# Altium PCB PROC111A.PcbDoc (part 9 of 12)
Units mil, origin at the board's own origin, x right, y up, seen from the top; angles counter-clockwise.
Board outline 7700 x 2300 mil, 6 copper layers (Top Layer, GND 1, SIG 1, SIG 2, GND 2, Bottom Layer), stack 61.062 mil thick; 841 components, 632 nets, 2914 pads, 1627 vias.
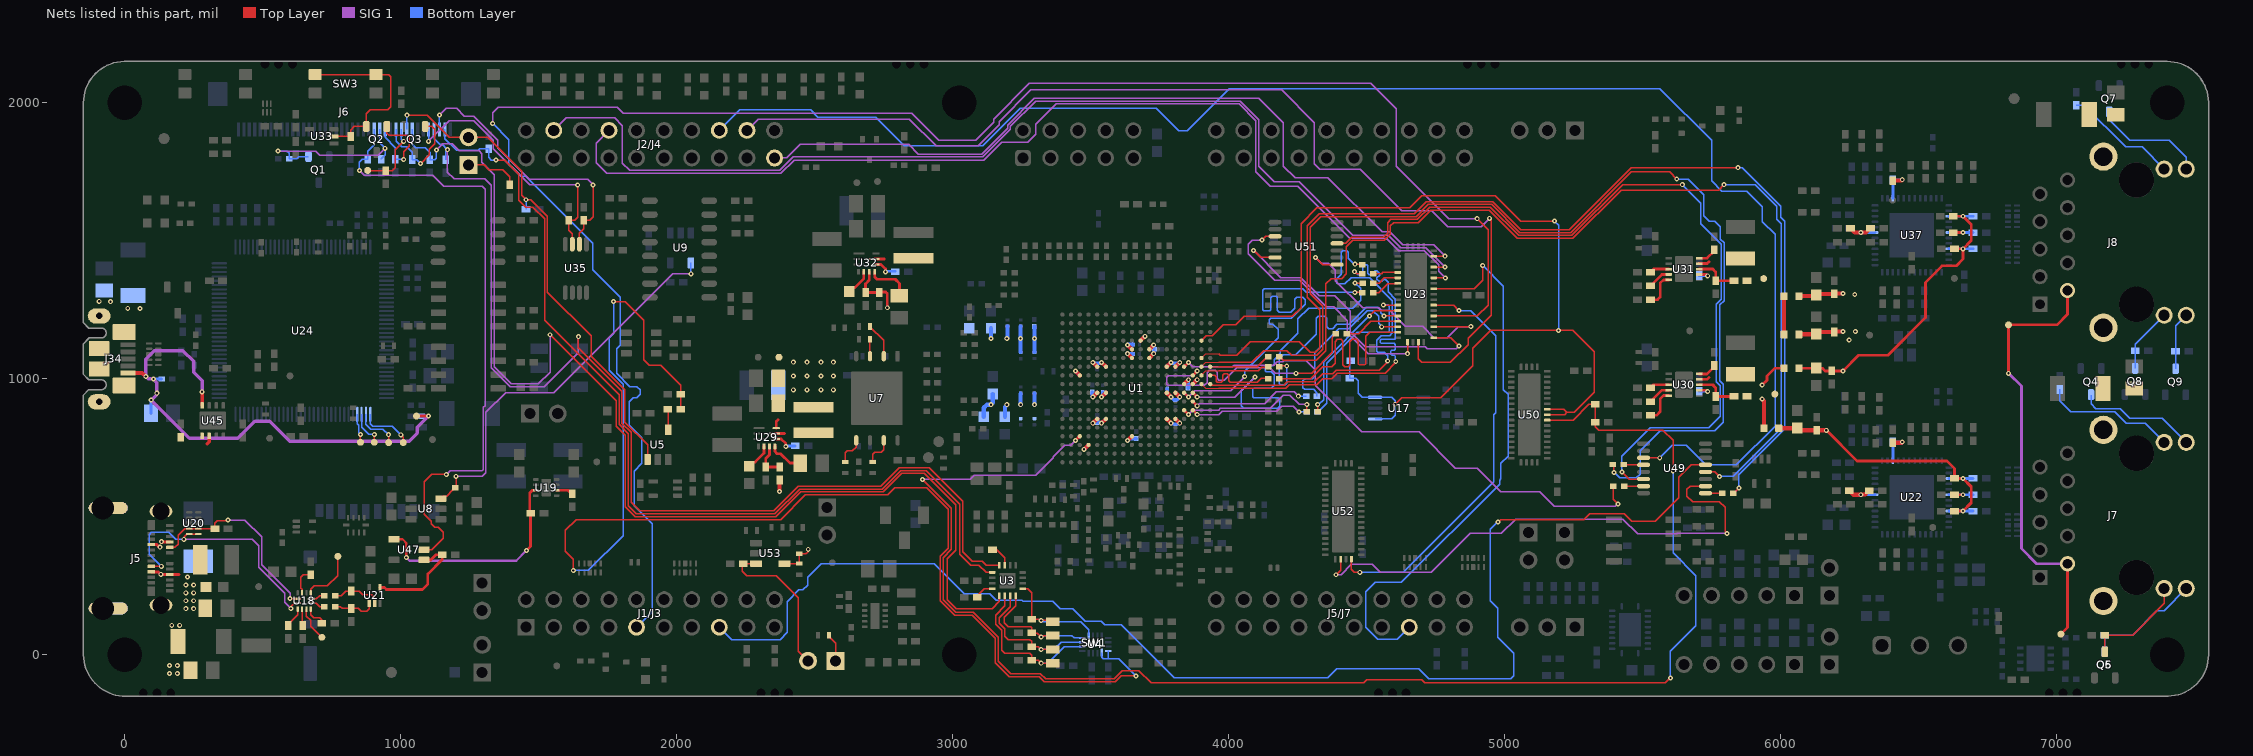
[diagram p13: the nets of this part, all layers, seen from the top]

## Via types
v1: diameter 18, hole 8, Top Layer to Bottom Layer, tented both sides, 1523 vias
v2: diameter 19.68, hole 7.87, Top Layer to Bottom Layer, tented both sides, 104 vias

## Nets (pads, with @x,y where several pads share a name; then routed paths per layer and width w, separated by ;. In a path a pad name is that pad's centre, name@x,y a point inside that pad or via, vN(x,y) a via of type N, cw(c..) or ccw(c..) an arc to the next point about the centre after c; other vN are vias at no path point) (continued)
PR0_PRU0_GPIO2_MUX: J2/J4.31 U23.37 | length 2924.8
  Top Layer w5.3: U23.37@4742.17,1444.29 v1(4783.82,1444.29)
  SIG 1 w4.75: J2/J4.31@2354.17,1800 2397.61,1800 2446.85,1849.25 2840.1,1849.25 2874.98,1814.38 3105.16,1814.38 3198.54,1907.75 3198.54,1919 3295.78,2016.24 4109.03,2016.24 4198.14,1927.13 4198.14,1770.95 4240,1729.09 4358.26,1729.09 4555.35,1532.01 4583.4,1532.01 4630.53,1484.88 4743.23,1484.88 v1(4783.82,1444.29)
PR0_PRU0_GPIO2_R: R362.2 U1.J18 | length 1445.3
  Top Layer w5.3: U1.J18@3936.86,976.53 4199.24,976.53 4211.41,988.7 4310.24,988.7 4340.2,1018.66 4376.66,1018.66 4389.34,1031.34 4544.23,1031.34 v1@4577.13,1064.23 ; v1(4456.95,1415.13) 4482.58,1415.13 R362.2@4483.84,1413.86
  Bottom Layer w5.3: v1(4456.95,1415.13) 4454.4,1415.13 4432.6,1436.93 4432.6,1458.32 4427.87,1463.04 4411.96,1463.04 4407.13,1458.21 4407.13,1378.9 4391.38,1363.15 4391.38,1346.71 4394.48,1343.61 4420.11,1343.61 4442.9,1366.4 4510.25,1366.4 4593.08,1283.57 4593.08,1166.13 4583.46,1156.51 4551.64,1156.51 4535.25,1140.12 4535.25,1099.96 4539.33,1095.89 4563.11,1095.89 4575.75,1083.25 v1(4575.75,1064.54)
PR0_PRU0_GPIO3: R363.1 U23.5 | length 91.7
  Top Layer w5.3: R363.1@4522.61,1380.23 4553.27,1380.23 4558.28,1385.24 U23.5@4612.24,1385.24
PR0_PRU0_GPIO3_MUX: J2/J4.19 U23.35 | length 3907.2
  Top Layer w5.3: U23.35@4742.17,1404.92 v1(4783.82,1404.92)
  SIG 1 w4.75: J2/J4.19@1554.17,1900 1599.17,1945 1775,1945 1802.52,1917.48 1802.52,1781.18 1828.84,1754.86 2373.2,1754.86 2422.76,1804.43 2744.16,1804.43 2744.26,1804.33 3109.33,1804.33 3208.59,1903.59 3208.59,1914.84 3299.94,2006.19 4041.54,2006.19 4109.36,1938.37 4109.36,1769.68 4165.04,1714 4254.5,1714 4448.27,1520.23 4578.26,1520.23 4623.66,1474.83 4713.91,1474.83 v1(4783.82,1404.92)
PR0_PRU0_GPIO3_R: R363.2 U1.J17 | length 1450.7
  Top Layer w4: U1.J17@3901.07,980.83 3915.96,965.93 3964.06,965.93
  Top Layer w5.3: 3964.06,965.93 4206.52,965.93 4218.69,978.1 4318.55,978.1 4340.2,999.75 4372.74,999.75 4393.73,1020.74 4566.37,1020.74 4604.93,1059.29 v1(4604.93,1062.23) ; v1(4455.35,1388.19) 4456.37,1388.19 4464.33,1380.23 R363.2@4483.24,1380.23
  Bottom Layer w5.3: v1(4455.35,1388.19) 4458.53,1388.19 4468.93,1377.79 4479.48,1377.79 4484.68,1382.99 4484.68,1410.53 4487.79,1413.63 4499.23,1413.63 4503.13,1409.73 4503.13,1382.99 4508.33,1377.79 4516.41,1377.79 4530.06,1391.44 4536.28,1391.44 4546.57,1381.15 4546.57,1375.74 4536.91,1366.08 4536.91,1361.28 4545.63,1352.56 4553.88,1352.56 4562.32,1361.01 4566.71,1361.01 4577.14,1350.57 4577.14,1314.5 4603.68,1287.97 4603.68,1145.87 4600.57,1142.76 4552.89,1142.76 4548.9,1138.78 4548.9,1131.39 4552.01,1128.29 4599.14,1128.29 4603.68,1123.75 4603.68,1107.22 4599.08,1102.62 4589.45,1102.62 4586.35,1099.51 4586.35,1090.84 4592.56,1084.63 4600.57,1084.63 4603.68,1081.52 4603.68,1063.48 v1(4604.93,1062.23)
PR0_PRU0_GPIO4: R364.1 U23.6 | length 95.6
  Top Layer w5.3: R364.1@4524.35,1346.94 4544.81,1346.94 4563.42,1365.55 U23.6@4612.24,1365.55
PR0_PRU0_GPIO4_MUX: J2/J4.17 U23.33 | length 3779.7
  Top Layer w5.3: U23.33@4742.17,1365.55 v1(4784.43,1365.55)
  SIG 1 w4.75: J2/J4.17@1754.17,1900 1707.86,1853.69 1707.86,1782.49 1745.68,1744.68 1850.9,1744.68 1851.03,1744.81 2377.36,1744.81 2424.77,1792.22 3111.43,1792.22 3176.48,1857.27 3271.87,1857.27 3301.39,1886.79 3301.39,1921.86 3375.68,1996.14 4037.37,1996.14 4097.74,1935.78 4097.74,1750.25 4150.49,1697.5 4249,1697.5 4437.79,1508.71 4571.14,1508.71 4615.07,1464.78 4709.05,1464.78 4761.11,1412.72 4761.11,1388.87 v1(4784.43,1365.55)
PR0_PRU0_GPIO4_R: R364.2 U1.K16 | length 1447.6
  Top Layer w5.3: v1(4457.69,1346.88) R364.2@4484.45,1346.88
  Top Layer w10: U1.K16@3869.57,949.33 v1(3885.32,933.58)
  SIG 1 w4.75: v1(3885.32,933.58) 4021.86,933.58 v1(4094.93,1006.66)
  Bottom Layer w5.3: v1(4094.93,1006.66) 4045.86,957.58 4045.86,902.83 4054.94,893.75 4177.59,893.75 4184.68,900.84 4184.68,924.64 4177.39,931.93 4089.86,931.93 4086.76,935.04 4086.76,963.19 4089.86,966.29 4154.39,966.29 4163.97,975.87 4163.97,1015.26 4153.19,1026.04 4135.7,1026.04 4132.6,1029.14 4132.6,1043.35 4135.7,1046.45 4159.11,1046.45 4163.97,1051.31 4163.97,1069.71 4186.11,1091.86 4186.11,1100.88 4250.6,1165.37 4250.6,1216.89 4289.61,1255.9 4449.12,1255.9 4477.36,1284.14 4477.36,1327.21 v1(4457.69,1346.88)
PR0_PRU0_GPIO5: R365.1 U49.4 | length 73.3
  Top Layer w5.3: R365.1@5430.12,689.41 5431.51,688.02 U49.4@5502.8,688.02
PR0_PRU0_GPIO5_MUX: J2/J4.13 U49.3 | length 5676.8
  Top Layer w5.3: U49.3@5502.8,713.61 v1(5561.38,713.61)
  Bottom Layer w5.3: J2/J4.13@2154.17,1900 2228.57,1974.4 2485.61,1974.4 2511.5,1948.51 2721.49,1948.51 2824.82,1845.18 3108.68,1845.18 3243.5,1980 3737.39,1980 3818.7,1898.69 3849.85,1898.69 4002.49,2051.32 5561.87,2051.32 5749.18,1864.02 5749.18,1716.82 5786.26,1679.74 5877.15,1679.74 5933.45,1623.44 5933.45,1569.28 5979.52,1523.21 5979.52,1381.91 5979.4,1381.79 5979.4,828.42 5838.86,687.88 5727.94,687.88 5657.09,758.73 5606.49,758.73 v1(5561.38,713.61)
PR0_PRU0_GPIO5_R: R365.2 U1.G17 | length 4016.3
  Top Layer w4: U1.G17@3901.07,1043.82 3916.82,1059.57 3964.06,1059.57
  Top Layer w5.3: 3964.06,1059.57 4083.8,1059.57 4126.4,1102.16 4210,1102.16 4227.29,1084.87 4318.46,1084.87 4340.12,1106.53 4340.12,1262.6 4294.48,1308.25 4294.48,1549.98 4332.35,1587.85 4678.93,1587.85 4722.85,1631.76 4952.38,1631.76 5054.14,1530.01 5238.26,1530.01 5458,1749.74 5596.83,1749.74 v1(5623.06,1723.51) ; R365.2@5390.75,689.41 5395.45,684.71 v1@5395.45,660.68
  Bottom Layer w5.3: v1(5395.79,660.75) 5415.66,640.87 5475.87,640.87 5490,655 5490,738.58 5562.99,811.57 5600,811.57 5600.59,810.98 5760,810.98 5791.6,842.58 5791.6,979.56 5778.19,992.97 5778.19,1220.57 5778.88,1221.26 5778.88,1267.41 5794.4,1282.93 5794.4,1492.39 5781,1505.79 5781,1551.74 5761.41,1571.33 5740.8,1571.33 5720.84,1591.29 5720.84,1666.95 5664.28,1723.51 v1(5623.06,1723.51)
PR0_PRU0_GPIO6: R366.1 U23.7 | length 103.5
  Top Layer w5.3: R366.1@4522.77,1312.1 4542.81,1312.1 4575.29,1344.58 4610.95,1344.58 U23.7@4612.24,1345.87
PR0_PRU0_GPIO6_MUX: J5/J7.48 U23.31 | length 2056.7
  Top Layer w5.3: U23.31@4742.17,1326.18 4890,1326.18 4920,1356.18 v1(4920,1410.88)
  Bottom Layer w5.3: J5/J7.48@4654.17,100 4610.54,56.37 4539.77,56.37 4496.8,99.34 4496.8,228.66 4530.09,261.96 4624.93,261.96 4980.81,617.84 4980.81,632.83 4985.6,637.62 4985.6,693.47 5011.9,719.76 5011.9,944.21 4995.12,960.98 4995.12,1335.75 v1(4920,1410.88)
PR0_PRU0_GPIO6_R: R366.2 U1.K15 | length 1440.8
  Top Layer w4.75: v1(4456.49,1313.1) 4482.4,1313.1 R366.2@4483.4,1312.1
  Top Layer w10: U1.K15@3838.08,949.33 v1(3853.83,933.58)
  SIG 1 w4.75: v1@3853.83,933.87 3875.81,955.85 3964.06,955.85 4006.32,955.85 4057.66,1007.19 v1(4057.66,1008.6)
  Bottom Layer w5.3: v1(4057.66,1008.6) 4057.66,1026.86 4178.64,1147.83 4178.64,1179.45 4159.74,1198.35 4150.25,1198.35 4147.14,1201.46 4147.14,1214.59 4151.87,1219.32 4226.16,1219.32 4276.91,1270.07 4276.91,1286.44 4268.6,1294.76 4245.6,1294.76 4239.19,1288.35 4239.19,1256.45 4223.97,1241.23 4182.8,1241.23 4175.75,1248.29 4175.75,1295.54 4172.57,1298.71 4156.77,1298.71 4151.58,1293.51 4151.58,1249.36 4148.47,1246.25 4126.42,1246.25 4122.16,1250.51 4122.16,1319.95 4128.49,1326.28 4268.22,1326.28 4281.4,1313.1 v1(4456.49,1313.1)
PR0_PRU0_GPIO8: R367.1 U49.7 | length 69.8
  Top Layer w5.3: R367.1@5433.02,611.25 U49.7@5502.8,611.25
PR0_PRU0_GPIO8_MUX: U49.6 U51.13 | length 2917.9
  Top Layer w5.3: U51.13@4392.2,1490.71 4423.61,1490.71 4445.26,1512.35 4559.74,1512.35 4575,1527.62 4575,1565 4587.25,1577.25 4683.32,1577.25 4727.24,1621.16 4947.99,1621.16 5049.75,1519.41 5242.65,1519.41 5426.49,1703.25 v1(5643.08,1703.25) ; v1(5424.59,662.43) 5450.18,636.84 U49.6@5502.8,636.84
  Bottom Layer w5.3: v1(5424.59,662.43) 5424.59,719.86 5526.9,822.17 5738.67,822.17 5781,864.5 5781,975.17 5766.48,989.69 5766.48,1270 5783.8,1287.32 5783.8,1488 5710.24,1561.56 5710.24,1636.09 v1(5643.08,1703.25)
PR0_PRU0_GPIO8_R: R367.2 U1.G15 | length 1921.7
  Top Layer w5.3: R367.2@5393.65,611.25 5393.65,562.94 v1(5410.28,546.31)
  Top Layer w10: U1.G15@3838.08,1043.82 v1(3853.83,1059.57)
  SIG 1 w4.75: v1(3853.83,1059.57) 3869.95,1043.45 4012.84,1043.45 4018.91,1049.52 4163.03,1049.52 4175.75,1062.23 4195.08,1062.23 4198.55,1065.7 4280.18,1065.7 4309.97,1035.92 4309.97,1035.85 4314,1031.82 4314,980 4314.46,979.54 4314.46,975.42 4482.24,807.64 4689.34,807.64 4821.11,675.87 4900.22,675.87 4985.88,590.21 5127.32,590.21 5180,537.52 5400.87,537.52 5409.67,546.31 v1(5410.28,546.31)
PR0_PRU0_GPIO9: R368.1 U49.9 | length 61.4
  Top Layer w5.3: U49.9@5727.2,585.66 5788.49,585.66 R368.1@5788.56,585.59
PR0_PRU0_GPIO9_MUX: U49.10 U52.40 | length 1959.6
  Top Layer w5.3: v1(4388.82,290) 4405.16,306.34 U52.40@4405.16,346.77 ; U49.10@5727.2,611.25 5671.25,611.25 5660,600 5660,575 5680.09,554.91 5777.05,554.91 5798,533.96 5798,447.48 v1(5805.48,440)
  SIG 1 w4.75: v1(4388.82,290) 4406.58,290 4444.53,327.95 4519.17,327.95 4548.27,298.84 4733.84,298.84 4875,440 4987.56,440 5039.29,491.73 5427.67,491.73 5481.08,438.31 5623.75,438.31 5625.43,440 v1(5805.48,440)
PR0_PRU0_GPIO9_R: R368.2 U1.F17 | length 4012.1
  Top Layer w4: U1.F17@3901.07,1075.32 3916.82,1091.06 3963.02,1091.06 3964.06,1090.02
  Top Layer w5.3: 3964.06,1090.02 3969.55,1084.53 4028.39,1084.53 4078.04,1134.18 4256.06,1134.18 4294.77,1095.47 4314.07,1095.47 4329.52,1110.92 4329.52,1249.39 4283.88,1295.04 4283.88,1554.37 4327.96,1598.45 4671.38,1598.45 4715.29,1642.36 4956.77,1642.36 5058.53,1540.61 5233.87,1540.61 5458.26,1765 v1(5845,1765) ; R368.2@5827.93,585.59 5829.89,585.59 v1@5847.68,603.38
  Bottom Layer w5.3: v1(5845,1765) 5860,1765 6000.65,1624.35 6000.65,1585.68 6015,1571.33 6015,819.05 5848.26,652.3 v1(5848.31,603.98) v1(5848.31,603.98)
PR0_PRU0_GPIO10: R286.1 U49.12 | length 3571.4
  Top Layer w5.3: R286.1@4181.94,1081.79 4196.57,1067.16 4316.85,1067.16 4350.72,1101.03 4350.72,1177.99 4350.99,1178.25 4350.99,1343.69 4370.56,1363.26 4408.89,1363.26 4425.91,1380.28 4425.91,1478.01 4449.65,1501.75 4564.13,1501.75 4585.6,1523.23 4585.6,1554 4597.06,1565.46 4687.31,1565.46 4732.41,1610.56 4943.6,1610.56 5045.36,1508.81 5247.04,1508.81 5421.96,1683.72 5774.62,1683.72 v1(5794.14,1703.25) ; U49.12@5727.2,662.43 5761.5,662.43 v1(5777.62,646.31)
  Bottom Layer w5.3: v1(5777.62,646.31) 5827.28,646.31 6002.02,821.06 6002.02,1561.6 5985.66,1577.96 5985.66,1624.35 5906.76,1703.25 v1(5794.14,1703.25)
PR0_PRU0_GPIO10_MUX: J1/J3.8 U49.13 | length 4804.6
  Top Layer w5.3: v1(4975,481.53) 4977.04,481.53 4984.45,488.94 5285.34,488.94 5307.81,511.41 5432.04,511.41 5459.88,483.56 5544.94,483.56 5630.1,568.72 5630.1,642.84 5675.28,688.02 U49.13@5727.2,688.02
  Bottom Layer w5.3: J1/J3.8@2154.17,100 2199.17,55 2374.5,55 2400.5,81 2400.5,192.8 2442.58,234.88 2456.8,234.88 2474.45,252.52 2474.45,281.15 2523.85,330.55 2932.19,330.55 3041.27,221.48 3134.1,221.48 3157.75,197.83 3250.44,197.83 3254.76,193.52 3362.89,193.52 3389.38,167.02 3434.43,167.02 3479.15,122.3 3538.25,122.3 3551.41,109.13 3610.51,109.13 3802.12,-82.48 4358.69,-82.48 4391.17,-50 4687.52,-50 4723.66,-86.14 5022.01,-86.14 5032.02,-76.13 5032.02,5.89 5011.07,26.83 4975,62.91 4975,168.75 4947.75,196 4947.75,454.27 v1(4975,481.53)
PR0_PRU0_GPIO10_R: R286.2 U1.G18 | length 225.7
  Top Layer w4: U1.G18@3932.57,1043.82 3964.06,1043.82
  Top Layer w5.3: 3964.06,1043.82 4102.62,1043.82 4140.6,1081.79 R286.2@4142.57,1081.79
PR0_PRU0_GPIO11: R75.1 U23.11 | length 633.4
  Top Layer w5.3: v1(4559.76,1267.13) U23.11@4612.24,1267.13
  Bottom Layer w5.3: R75.1@4323.25,879.85 4354.23,910.84 4354.23,1057.24 4465.86,1168.86 4578.68,1168.86 4581.95,1172.14 4581.95,1262.78 4576.72,1268.01 4560.65,1268.01 v1(4559.76,1267.13)
PR0_PRU0_GPIO11_MUX: U23.28 U52.42 | length 1496.2
  Top Layer w5.3: U52.42@4444.53,346.77 4444.53,309.12 4454.81,298.84 v1(4474.81,298.84) ; U23.28@4742.17,1267.13 4814.13,1267.13 v1(4833.82,1247.44)
  Bottom Layer w5.3: v1(4474.81,298.84) 4631.83,298.84 4959.61,626.62 4959.61,869.96 4967.27,877.62 4967.27,1155.63 4876.09,1246.81 4834.45,1246.81 v1(4833.82,1247.44)
PR0_PRU0_GPIO11_R: R75.2 U1.M16 | length 439.5
  Top Layer w10: U1.M16@3869.57,886.34 v1(3885.32,870.59)
  SIG 1 w4.75: v1(3885.32,870.59) 3963.53,870.59 3975.51,882.57 4173.77,882.57 4191.27,900.07 4233.67,900.07 v1(4253.87,879.87)
  Bottom Layer w5.3: v1(4253.87,879.87) R75.2@4281.93,879.87
PR0_PRU0_GPIO12: R76.1 U23.12 | length 538.7
  Top Layer w5.3: R76.1@4321.93,879.87 v1(4321.93,906.95) ; v1(4509.76,1227.76) 4529.45,1247.44 U23.12@4612.24,1247.44
  Bottom Layer w5.3: v1(4321.93,906.95) 4325.96,906.95 4343.63,924.62 4343.63,1061.63 v1(4509.76,1227.76)
PR0_PRU0_GPIO12_MUX: J1/J3.5 U23.26 | length 6811.1
  Top Layer w5.3: U23.26@4742.17,1227.76 4901.06,1227.76 4939.52,1266.23 4939.52,1540.48 v1(4900,1580)
  SIG 1 w4.75: v1(1333,1925) 1333,1964.79 1352.43,1984.22 1784.16,1984.22 1806.7,1961.69 2852.04,1961.69 2948.55,1865.18 3083.36,1865.18 3147.74,1929.55 3147.74,1940.05 3277.69,2070 4515,2070 4606.5,1978.5 4606.5,1770.5 4797,1580 v1(4900,1580)
  Bottom Layer w5.3: v1(1333,1925) 1391,1867 1391,1776.77 1434.27,1733.5 1453,1733.5 1695,1491.5 1695,1395 1794.52,1295.48 1794.52,1121.36 1781.78,1108.62 1781.78,1019.79 1830.4,971.17 1855.77,971.17 1867.21,959.73 1867.21,943.56 1855.34,931.69 1842.81,931.69 1827.82,916.71 1827.82,831.22 1873.54,785.51 1873.54,694.12 1845,665.58 1845,539.99 1910.68,474.31 1910.68,156.51 J1/J3.5@1854.17,100
PR0_PRU0_GPIO12_R: R76.2 U1.M15 | length 521.3
  Top Layer w5.3: R76.2@4282.56,879.87 v1(4282.56,906.95)
  Top Layer w10: U1.M15@3838.08,886.34 v1(3853.83,870.59)
  SIG 1 w4.75: v1(3853.83,870.59) 3869.95,886.71 3963.69,886.71 3969.6,892.62 4149.62,892.62 4197.89,940.9 4220.68,940.9 4254.62,906.95 v1(4282.56,906.95)
PR0_PRU0_GPIO13: R77.1 U23.13 | length 821.5
  Top Layer w5.3: R77.1@4181.84,1046.45 v1(4209.91,1046.45) ; v1(4562.19,1227.6) 4562.27,1227.68 4612.16,1227.68 U23.13@4612.24,1227.76
  Bottom Layer w5.3: v1@4210,1041.33 4210,984.12 4204.1,978.22 4186.66,978.22 4183.55,981.32 4183.55,1074.31 4196.45,1087.21 4243.4,1087.21 4317.17,1160.97 4317.17,1220.24 4323.67,1226.74 4347.43,1226.74 4354.17,1220 4354.17,1189.45 4361.88,1181.74 4375.94,1181.74 4391.38,1197.18 4436.06,1197.18 4497.7,1258.82 4539.53,1258.82 4549.65,1248.7 4549.65,1240.14 v1(4562.19,1227.6)
PR0_PRU0_GPIO13_MUX: U23.24 U51.10 | length 945.6
  Top Layer w5.3: v1(4314,1439.53) 4339.59,1413.94 U51.10@4392.2,1413.94 ; U23.24@4742.17,1188.39 4876.38,1188.39 v1(4876.97,1188.98)
  SIG 1 w4.75: v1(4314,1439.53) 4334.37,1419.15 4360.85,1419.15 4386.56,1393.44 4386.56,1355.4 4484.9,1257.06 4542.61,1257.06 4551.79,1247.88 4582.53,1247.88 4639.58,1190.83 4701.94,1190.83 4743.32,1149.45 4791.79,1149.45 4831.16,1188.82 4876.82,1188.82 v1(4876.97,1188.98)
PR0_PRU0_GPIO13_R: R77.2 U1.H17 | length 253.5
  Top Layer w4: U1.H17@3901.07,1012.32 3917.21,1028.46 3964.06,1028.46
  Top Layer w5.3: 3964.06,1028.46 4107.13,1028.46 4120,1041.33 R77.2@4142.57,1041.33
PR0_PRU0_GPIO14: R78.1 U23.14 | length 204
  Top Layer w5.3: R78.1@4426.85,1163.21 4470,1163.21 4514.86,1208.07 U23.14@4612.24,1208.07
PR0_PRU0_GPIO14_MUX: U23.22 U51.6 | length 1132
  Top Layer w5.3: v1(4089.59,1465.12) 4115.18,1439.53 U51.6@4167.8,1439.53 ; U23.22@4742.17,1149.02 4804.13,1149.02 v1(4833.82,1119.33)
  SIG 1 w4.75: v1(4089.59,1465.12) 4187.74,1366.97 4260.95,1366.97 4327.16,1300.76 4384.36,1300.76 4440.05,1245.06 4440.05,1170.83 4494.16,1116.72 4711.82,1116.72 4719.29,1109.25 4823.74,1109.25 v1(4833.82,1119.33)
PR0_PRU0_GPIO14_R: R78.2 U1.H16 | length 970.7
  Top Layer w5.3: v1(4243.4,1020) 4299.67,1020 4375,1095.33 4375,1150.74 R78.2@4387.48,1163.21
  Top Layer w10: U1.H16@3869.57,1012.32 v1(3885.32,1028.07)
  SIG 1 w4.75: v1(3885.32,1028.07) 3869.2,1011.95 3781.22,1011.95 3775.46,1006.19 3775.46,980.74 3780.01,976.19 3911.04,976.19 3921.29,986.43 3921.29,1022.13 3930.07,1030.91 3951.11,1030.91 3957.9,1024.12 3957.9,1001.23 3964.06,995.07 3964.11,995.02 3984.31,995.02 4028.76,1039.47 4148.35,1039.47 4167.82,1020 v1(4243.4,1020)
PR0_PRU0_GPIO15: R79.1 U23.15 | length 635
  Top Layer w5.3: v1(4554.04,1188.39) U23.15@4612.24,1188.39
  Bottom Layer w5.3: R79.1@4319.35,936.88 4319.35,950 4307.97,961.38 4275.19,961.38 4268.22,968.35 4268.22,992.35 4276.35,1000.48 4301.81,1000.48 4311.67,1010.33 4311.67,1095.15 4397.65,1181.13 4435,1181.13 4501.15,1247.28 4521.44,1247.28 4542.74,1225.99 4542.74,1201.06 4554.04,1189.76 v1(4554.04,1188.39)
PR0_PRU0_GPIO15_MUX: J2/J4.12 U23.20 | length 3909.3
  Top Layer w5.3: U23.20@4687.05,1133.27 4687.05,1072.45 4699.93,1059.57 4802.79,1059.57 4867.02,1123.8 4867.02,1147.5 4950.12,1230.6 4950.12,1576.43 v1(4945,1581.55)
  SIG 1 w4.75: J2/J4.12@2254.17,1900 2295.21,1941.04 2843.09,1941.04 2939.6,1844.53 3091.91,1844.53 3168.39,1921 3168.39,1931.49 3283.29,2046.39 4191.2,2046.39 4309.59,1928.01 4309.59,1779.65 4330,1759.24 4476.07,1759.24 4626.68,1608.62 4736.03,1608.62 4793.54,1551.11 4914.55,1551.11 v1(4945,1581.55)
PR0_PRU0_GPIO15_R: R79.2 U1.L16 | length 444.1
  Top Layer w10: U1.L16@3869.57,917.83 v1(3885.32,902.09)
  SIG 1 w4.75: v1(3885.32,902.09) 3893.24,910 4130,910 4172.33,952.33 4236.47,952.33 v1(4251.92,936.88)
  Bottom Layer w5.3: v1(4251.92,936.88) R79.2@4279.98,936.88
PR0_PRU0_GPIO16: R80.1 U23.16 | length 911.4
  Top Layer w5.3: R80.1@4181.94,1001.33 4182.79,1000.48 4297.03,1000.48 4339.83,1043.28 4373.26,1043.28 4385.6,1055.63 4385.6,1135 4393.45,1142.85 4407.03,1142.85 4413.14,1136.74 4413.14,1050.44 4419.39,1044.19 4432.16,1044.19 4439.07,1051.1 4439.07,1135.11 4446.81,1142.85 4461,1142.85 4469.2,1134.65 4469.2,1053.48 4472.3,1050.37 4492.4,1050.37 4495.5,1053.48 4495.5,1154.05 4510.15,1168.7 U23.16@4612.24,1168.7
PR0_PRU0_GPIO16_MUX: U23.18 U51.3 | length 940.3
  Top Layer w5.3: v1(4120,1502.62) 4133.68,1516.3 U51.3@4167.8,1516.3 ; v1(4647.68,1091.01) U23.18@4647.68,1133.27
  SIG 1 w4.75: v1(4120,1502.62) 4084.29,1502.62 4070,1488.33 4070,1452.91 4165.98,1356.92 4256.78,1356.92 4353.27,1260.44 4379.56,1260.44 4430,1210 4430,1166.2 4505.19,1091.01 v1(4647.68,1091.01)
PR0_PRU0_GPIO16_R: R80.2 U1.H18 | length 285.1
  Top Layer w5.3: U1.H18@3932.57,1012.32 3949.55,1012.32 3953.77,1008.1 3953.77,991.12 3957.76,987.13 3972.13,987.13 3977.72,992.72 3977.72,1012.11 3983.48,1017.86 3994.81,1017.86 4000,1012.67 4000,992.13 4005,987.13 4103.02,987.13 4117.22,1001.33 R80.2@4142.57,1001.33
QSPI0_D2: R29.1 U7.3 | length 61.6
  Top Layer w5.3: R29.1@2699.68,1143.54 2699.68,1082.39 U7.3@2700,1082.08
QSPI0_D3: R30.1 U7.7 | length 109.1
  Top Layer w5.3: R30.1@2710,698.65 2710,726.52 2716.97,733.49 2741.34,733.49 2750,742.15 U7.7@2750,776.92
QSPI_D0: R27.1 U7.5 | length 105.7
  Top Layer w5.3: R27.1@2610,698.65 2610,731.33 2618.06,739.39 2636.59,739.39 2650,752.8 U7.5@2650,776.92
QSPI_D1: R28.1 U7.2 | length 128
  Top Layer w5.3: R28.1@2699.68,1189.27 2750,1138.95 U7.2@2750,1082.08
RESETN_PB: Q2.2 R178.1 SW3.2 SW3.4 U33.2 | length 678.4
  Top Layer w5.3: SW3.2@689.76,2102.28 SW3.4@910.24,2102.28 956.81,2102.28 964.09,2095 964.09,1985 953.05,1973.95 888.54,1973.95 874.85,1960.27 Q2.2@874.85,1914.27 831.22,1914.27 818.08,1901.13 R178.1@818.08,1878.15 U33.2@757.66,1878.15
RGMII1_ICSSM_MUX_EN_GPIO1: R292.2 R294.2 U1.R3 U50.8 | length 5497.5
  Top Layer w5.3: v1(2890,635.56) 2995,530.56 2995,382.3 2965,352.3 2965,200 3010.61,154.39 3074.11,154.39 3164.77,63.73 3164.77,-24.03 3209.09,-68.35 3317.38,-68.35 3336.17,-87.14 3584.71,-87.14 3614.73,-57.13 3673.8,-57.13 3718.78,-102.1 4488.62,-102.1 4500.72,-90 4698.33,-90 4710.43,-102.1 5581.48,-102.1 v1(5600,-83.58) ; U50.8@5153.35,850.35 5247.83,850.35 5304.5,907.02 R292.2@5327.76,907.02 R294.2@5327.76,842.02 5327.76,826.31 5339.74,814.33 5572.88,814.33 5610,777.2 v1(5610,665.75)
  Top Layer w10: v1(3444.38,776.1) U1.R3@3460.12,791.85
  SIG 1 w4.75: v1(2890,635.56) 3062.81,635.56 3078.06,650.8 3301.39,650.8 3363.8,713.22 3363.8,718.03 3405.76,759.98 3428.26,759.98 v1(3444.38,776.1)
  Bottom Layer w5.3: v1(5600,-83.58) 5600,12.32 5692.18,104.5 5692.18,286.97 5610,369.15 v1(5610,665.75)
RGMII1_ICSSM_MUX_SEL_GPIO105: R291.2 R293.2 U1.D17 U17.1 U17.5 U50.9 U50.10 | length 3866.3
  Top Layer w5.3: U1.D17@3901.07,1138.31 3918.04,1155.28 3940.41,1155.28 3980.23,1195.1 4025.07,1195.1 4056.07,1226.1 4230.76,1226.1 4261.7,1257.04 4261.7,1562.17 4319.17,1619.65 4654.94,1619.65 4698.85,1663.56 4965.55,1663.56 5058.39,1570.73 5059.1,1571.45 v1(5180,1571.45) ; v1(4602.96,907.75) 4626.02,930.8 4767.18,930.8 4884.52,1048.14 4884.52,1109.78 4949.74,1175 v1(5195,1175) 5247.09,1175 5324.89,1097.19 5324.89,950.86 5252.46,878.43 5224.87,878.43 ; U50.9@5153.35,870.04 5216.48,870.04 5224.87,878.43 ; U50.10@5153.35,889.72 5213.57,889.72 5224.87,878.43
  Bottom Layer w5.3: R293.2@4441.64,1065.33 4438.62,1062.32 R291.2@4438.62,1002.36 4460,1002.36 4468.69,993.67 4468.69,947.35 4482.92,933.12 U17.5@4530.08,933.12 4590.77,933.12 4602.86,921.02 4602.86,907.85 v1(4602.96,907.75) 4602.84,907.62 4602.84,867.37 4589.85,854.38 U17.1@4530.08,854.38 ; v1(5180,1571.45) 5195,1556.45 v1(5195,1175)
RJ45_1_LED1_GREEN: J7.11 R224.2 | length 482.1
  Bottom Layer w5.3: R224.2@7010.2,961.38 7010.2,920.65 7050.85,880 7210,880 7251.78,838.22 7320.62,838.22 J7.11@7389.08,769.76
RJ45_1_LED1_YELLOW: J7.12 Q4.3 | length 433.3
  Bottom Layer w5.3: Q4.3@7124.1,940.04 7124.1,909.48 7141.58,891.99 7229.47,891.99 7264.47,856.99 7381.77,856.99 J7.12@7469,769.76
RJ45_1_LED2_GREEN: J7.13 Q5.3 R226.1 | length 377.3
  Top Layer w5.3: Q5.3@7174,10.9 R226.1@7174,71.46 7274.43,71.46 7389.08,186.1 J7.13@7389.08,240.24
RJ45_1_LED2_YELLOW: J7.14 Q6.3 R228.1 | length 425.5
  Bottom Layer w5.3: Q6.3@7174,10.9 R228.1@7174,71.46 7274.43,71.46 7362.97,160 7388.76,160 J7.14@7469,240.24
RJ45_1_VCC: J7.2 J8.2 TP21.1 TP22.1 | length 1601.1
  Top Layer w10: v1(6825,1020) TP21.1@6825,1195.45 7000.65,1195.45 7039.08,1233.88 J8.2@7039.08,1320 ; TP22.1@7015,75 7039.08,99.08 J7.2@7039.08,330
  SIG 1 w10: v1(6825,1020) 6871.66,973.34 6871.66,385 6926.66,330 J7.2@7039.08,330
RJ45_2_LED1_GREEN: J8.11 R230.2 | length 415
  Bottom Layer w5.3: R230.2@7070,1991.38 7097.83,1991.38 7249.21,1840 7308.84,1840 J8.11@7389.08,1759.76
RJ45_2_LED1_YELLOW: J8.12 Q7.3 | length 407.6
  Bottom Layer w5.3: Q7.3@7190,1967.76 7190,1938.61 7263.61,1865 7407.14,1865 7469,1803.14 J8.12@7469,1759.76
RJ45_2_LED2_GREEN: J8.13 Q8.3 R232.1 | length 235.9
  Bottom Layer w5.3: Q8.3@7283.87,1037.91 R232.1@7283.87,1101.28 7283.87,1125.03 J8.13@7389.08,1230.24
RJ45_2_LED2_YELLOW: J8.14 Q9.3 R234.1 | length 209.6
  Bottom Layer w5.3: Q9.3@7430.33,1036.64 R234.1@7430.33,1100 7430.33,1191.56 J8.14@7469,1230.24
SD_PWR_EN: R39.2 U8.3 U9.4 | length 1434.3
  Top Layer w5.3: U8.3@1145.16,566 1154.32,575.16 1165.71,575.16 1188.16,597.61 1190.36,597.61 1200.2,607.45 v1(1200.2,646.72)
  SIG 1 w4.75: v1(1200.2,646.72) 1294.46,646.72 1308.14,660.4 1308.14,878.79 1379.57,950.21 1554.67,950.21 1795,1190.54 1795.21,1190.54 1985,1380.33 v1(2051.37,1380.33)
  Bottom Layer w5.3: v1(2051.37,1380.33) U9.4@2051.37,1420.16
SHIELD1: C229.2 J5.1 J5.2 J5.3 J5.4 R32.1
  other v1: 161.53,-67.94 190.2,-67.94 161.53,-39.28 190.2,-39.28 170.14,106.73 198.8,106.73
SHIELD2: C235.2 J7.15 J7.16 R254.1
SHIELD3: C247.2 J8.15 J8.16 R255.1
SHIELD4: C230.2 J34.6 J34.7 J34.8 J34.9 J34.10 J34.11 R253.1
  other v1: 10.71,1255.26 55.5,1255.13 -51.58,1279.52 -92.91,1280.67
SOC_TA_I2C3_SCL: J6.36 R192.1 U35.7 | length 977.1
  Top Layer w5.3: U35.7@1621.58,1487.6 1621.58,1525.59 1608.28,1538.89 R192.1@1608.28,1574.72 1630.75,1574.72 1640.94,1584.91 v1(1640.94,1702.17)
  SIG 1 w5.3: v1(1100,1860.39) 1175.11,1935.5 1264.6,1935.5 1335.5,1864.6 1335.5,1833.2 1466.53,1702.17 v1(1640.94,1702.17)
  Bottom Layer w5.3: v1(1100,1860.39) 1100.75,1861.14 J6.36@1100.75,1903.35
SOC_TA_I2C3_SDA: J6.38 R190.1 U35.6 | length 996.7
  Top Layer w5.3: U35.6@1647.17,1487.6 1647.17,1528.19 1663.28,1544.3 R190.1@1663.28,1574.72 1684.22,1574.72 1696.52,1587.03 v1(1696.52,1702.17)
  SIG 1 w5.3: v1(1140.12,1955.5) 1164.14,1979.52 1201.98,1979.52 1230.03,1951.47 1263.62,1951.47 1350.5,1864.59 1350.5,1837.29 1465.64,1722.14 1676.55,1722.14 v1(1696.52,1702.17)
  Bottom Layer w5.3: J6.38@1140.12,1903.35 v1(1140.12,1955.5)
SOP0_SW: R14.2 SW1.8 U3.2 U4.6 | length 609.8
  Top Layer w5.3: U3.2@3188.21,213.58 3188.21,177.25 3155,144.04 3155,110.21 3176.57,88.64 3176.57,16.63 3188.37,4.82 3279.69,4.82 3285.55,-1.03 R14.2@3285.55,-20.49 3309.25,-20.49 3319.25,-30.49 v1(3320.3,-30.49) SW1.8@3362.3,-30.49
  Bottom Layer w5.3: v1(3320.3,-30.49) 3344.01,-30.49 3404.41,29.91 U4.6@3468.83,29.91
SOP1_SW: R15.2 SW1.7 U3.3 U4.7 | length 536.3
  Top Layer w5.3: U3.3@3207.9,213.58 3207.9,174.9 3167.5,134.5 3167.5,113.84 3187.66,93.69 3187.66,67.78 3200.61,54.82 3279.69,54.82 3285.55,48.97 R15.2@3285.55,29.51 3309.25,29.51 3319.25,19.51 v1(3320.3,19.51) SW1.7@3362.3,19.51
  Bottom Layer w5.3: v1(3320.3,19.51) 3366.01,19.51 3392.15,45.65 U4.7@3468.83,45.65
SOP2_SW: R16.2 SW1.6 U3.4 U4.8 | length 477.2
  Top Layer w5.3: U3.4@3227.58,213.58 3227.58,177.08 3186,135.5 3186,116.58 3200.89,101.69 3282.45,101.69 3285.55,98.59 R16.2@3285.55,79.51 3286.4,78.66 3306.14,78.66 v1(3320.3,64.51) 3323.74,64.51 3328.74,69.51 SW1.6@3362.3,69.51
  Bottom Layer w5.3: v1@3320.3,69.51 3431.42,69.51 3439.52,61.4 U4.8@3468.83,61.4
SOP3_SW: R17.2 SW1.5 U3.5 U4.9 | length 420.1
  Top Layer w5.3: U3.5@3253.17,239.17 3272,239.17 3285.55,225.62 R17.2@3285.55,129.51 3311.86,129.51 3316.86,124.51 v1(3320.3,124.51) 3357.3,124.51 SW1.5@3362.3,119.51
  Bottom Layer w5.3: v1@3320.3,119.51 3462.96,119.51 3492.45,90.02 U4.9@3492.45,69.28
SOP_DRIVE_OEN_R: R18.1 U5.4 | length 74.2
  Top Layer w5.3: R18.1@1967.18,889.07 1968.71,887.54 U5.4@1968.71,815.53
SOP_DRIVER_OEN: R18.2 R20.1 U4.1 U4.16 | length 4721.4
  Top Layer w5.3: v1(1625,305.6) 1625,345.92 1595.98,374.93 1595.98,450.43 1634.98,489.43 2376.14,489.43 2466,579.29 2764.74,579.29 2790.09,604.64 2905.93,604.64 2983.45,527.12 2983.45,385.73 2954.4,356.69 2954.4,195.61 3006.22,143.79 3069.72,143.79 3154.17,59.34 3154.17,-28.42 3204.7,-78.95 3312.98,-78.95 3331.78,-97.74 3589.1,-97.74 3610.2,-76.65 v1(3663.63,-76.65) ; v1(1771.18,1279.68) 1812.46,1279.68 1880,1212.14 1880,1069.59 1900,1049.59 1942.36,1049.59 2014.43,977.52 R20.1@2014.43,944.07 R18.2@2014.43,889.07
  Bottom Layer w5.3: v1(1625,305.6) 1679.88,305.6 1805.64,431.36 1805.64,980.93 1755.48,1031.1 1755.48,1148.97 1771.18,1164.67 v1(1771.18,1279.68) ; U4.1@3539.69,8.25 3540.02,7.93 3540.02,-9.79 3544.52,-14.29 3563.32,-14.29 ; U4.16@3563.32,14.16 3563.32,-14.29 ; v1(3663.63,-76.65) 3601.27,-14.29 3563.32,-14.29
TA_GPIO1: J6.30 Q3.1 R185.2 | length 364.2
  Top Layer w5.3: v1(1071.4,1780) 1102.5,1811.1 1102.5,1832 1122.5,1852 1122.5,1903.96 1112.19,1914.27 Q3.1@1088.52,1914.27
  Bottom Layer w5.3: J6.30@982.64,1903.35 982.64,1860 1002.64,1840 1022.01,1840 1040.9,1821.1 R185.2@1040.9,1794.53 1041.59,1793.84 1057.56,1793.84 v1(1071.4,1780)
TA_GPIO2: J6.31 R184.2 TP18.1 | length 259.7
  Top Layer w5.3: TP18.1@880,1755 881.38,1753.62 R184.2@944.86,1753.62 968.66,1753.62 980.5,1765.46 980.5,1830.36 v1(1010.53,1860.39)
  Bottom Layer w5.3: J6.31@1002.32,1903.35 1002.32,1868.6 v1(1010.53,1860.39)
TA_GPIO3: J1.2 J6.32 R183.2 U5.1 | length 1828.8
  Top Layer w5.3: v1(1022.01,1955) 1095,1955 1175,1875 J1.2@1245.54,1875 1314.64,1875 1437.99,1751.65 1437.99,1664.55 v1(1453.77,1648.77) 1470.75,1648.77 1531.34,1588.18 1531.34,1314.38 1689.67,1156.04 1689.67,1081.54 1811.8,959.42 1811.8,843.2 1893.91,761.09 U5.1@1893.91,707.27
  Bottom Layer w5.3: J6.32@1022.01,1903.35 v1(1022.01,1955) ; R183.2@1453.77,1615 v1(1453.77,1648.77)
TA_GPIO3_PD: J1.1 R21.2 | length 195.5
  Top Layer w5.3: J1.1@1245.54,1775 1301.5,1775 1319,1757.5 1368.67,1757.5 1395,1731.17 R21.2@1395,1703.25
TA_GPIO4: J6.33 R182.2 U3.1 | length 4222.7
  Top Layer w5.3: v1(1540.74,1159.56) 1780,920.3 1780,828.8 1813.29,795.51 1813.29,535.87 1849.14,500.03 2359.3,500.03 2449.16,589.89 2748.07,589.89 2815.13,656.95 2897.2,656.95 3010,544.16 3010,378.06 2980,348.06 2980,200 3012.82,167.18 3142.18,167.18 3168.53,193.53 U3.1@3168.53,213.58
  SIG 1 w5.3: v1(1129,1828.5) 1151.5,1851 1186.5,1851 1211,1826.5 1283.5,1826.5 1294,1816 1294,1784.5 1338.5,1740 1338.5,1044.16 1400.93,981.74 1498.84,981.74 1540.74,1023.64 v1(1540.74,1159.56)
  Bottom Layer w5.3: J6.33@1041.69,1903.35 1041.69,1850 1053.9,1837.8 1087.7,1837.8 1106.5,1819 1106.5,1795.12 R182.2@1105,1793.62 1123.62,1793.62 1129,1799 v1(1129,1828.5)
TA_I2C_SCL: J6.37 R191.1 U3.12 | length 3857.8
  Top Layer w5.3: v1(1643.39,1152.62) 1643.39,1112.84 1801.2,955.03 1801.2,838.81 1834.49,805.52 1834.49,552.32 1865.59,521.23 2350.52,521.23 2440.38,611.09 2739.29,611.09 2806.35,678.15 2914.42,678.15 3035.98,556.59 3035.98,373.5 3071.26,338.21 3107.55,338.21 3121.94,323.82 U3.12@3168.53,323.82
  SIG 1 w5.3: v1(1169,1830) 1169,1748.5 1193,1724.5 1304.5,1724.5 1327.9,1701.1 1327.9,1039.77 1396.53,971.14 1519.72,971.14 1643.39,1094.8 v1(1643.39,1152.62)
  Bottom Layer w5.3: J6.37@1120.43,1903.35 1120.43,1869.07 1140.5,1849 1150,1849 v1(1169,1830) 1162.52,1823.52 R191.1@1162.52,1793.62
TA_I2C_SDA: J6.39 R189.1 U3.13 | length 3412.6
  Top Layer w5.3: v1(1345,1792.32) 1376.45,1792.32 1427.39,1741.38 1427.39,1647.54 1452.96,1621.97 1478.04,1621.97 1520.74,1579.27 1520.74,1212.73 1790.6,942.87 1790.6,834.42 1823.89,801.13 1823.89,540.26 1853.53,510.63 2354.91,510.63 2444.77,600.49 2743.68,600.49 2810.74,667.55 2903.7,667.55 3025.38,545.87 3025.38,364.62 3065,325 3093.65,325 3120.42,298.23 U3.13@3142.94,298.23
  Bottom Layer w5.3: J6.39@1159.8,1903.35 1159.8,1870.2 1202.5,1827.5 1280.5,1827.5 1286.38,1833.38 R189.1@1318,1833.38 1318,1802.5 1328.18,1792.32 v1(1345,1792.32)
TA_PORZ: J6.27 Q1.1 R180.1 R187.2 | length 663.3
  SIG 1 w5.3: v1(555,1825) 692.56,1825 707.14,1810.43 918.69,1810.43 v1(943.27,1835)
  Bottom Layer w5.3: v1(555,1825) 587.44,1825 595.37,1817.07 R180.1@595.37,1797.32 623.09,1797.32 630.77,1805 Q1.1@665.58,1805 ; J6.27@923.58,1903.35 923.58,1855 943.27,1835.32 v1(943.27,1835) 943.27,1811.2 929.84,1797.78 R187.2@929.84,1795
TA_POWERDOWNZ: J6.26 R188.2 U47.2 | length 2243.2
  Top Layer w5.3: U47.2@1083.63,381 1112.79,381 1153.42,421.63 1153.42,444.12 1135.01,462.53 1122.68,462.53 1111.18,474.02 1111.18,483.9 1085.48,509.6 1085.48,627.1 1111.88,653.5 v1@1165.63,653.5
  SIG 1 w4.75: v1(850,1755) 867.5,1737.5 1115.5,1737.5 1155.5,1697.5 1294.59,1697.5 1305.16,1686.93 1305.16,903.16 1298.09,896.09 1298.09,669.93 1294.13,665.97 1179.61,665.97 v1@1166.18,652.54
  Bottom Layer w5.3: v1(850,1755) 850,1785 860,1795 R188.2@879.84,1795 879.84,1823.58 903.9,1847.64 J6.26@903.9,1903.35
  other v1: 1164.85,653.5
TA_RESETZ: J6.28 Q2.1 R186.2 | length 353.8
  Top Layer w5.3: Q2.1@949.65,1914.27 949.94,1913.98 949.94,1889.74 957.42,1882.26 1023.98,1882.26 1030.06,1876.19 1030.06,1842.97 1010.53,1823.45 v1(1010.53,1795)
  Bottom Layer w5.3: J6.28@943.27,1903.35 943.27,1874.37 979.84,1837.8 R186.2@979.84,1795 v1(1010.53,1795)
TCA_ADDR: R10.2 U3.16 | length 64.9
  Top Layer w5.3: R10.2@3088.62,213.58 3114.21,239.17 U3.16@3142.94,239.17
TCA_INTN: R11.2 U3.11 | length 84.6
  Top Layer w5.3: R11.2@3143.62,380.76 3159.37,380.76 3188.21,351.92 U3.11@3188.21,323.82
TM4C129_TCK: TP27.1 U24.100 | length 106
  Top Layer w5.3: TP27.1@853.9,770 v1(853.9,798.54)
  Bottom Layer w5.3: U24.100@842.35,871.22 842.35,837.26 847.01,832.59 847.01,805.43 v1(853.9,798.54)
TM4C129_TDI: TP29.1 U24.98 | length 161.9
  Top Layer w5.3: TP29.1@955.9,769 v1(955.9,797.54)
  Bottom Layer w5.3: U24.98@873.85,871.22 873.85,835.75 891.53,818.07 935.37,818.07 v1(955.9,797.54)
TM4C129_TDO: TP30.1 U24.97 | length 192.8
  Top Layer w5.3: v1(1000,797.13) 1000,796.57 1008.9,787.67 TP30.1@1008.9,769
  Bottom Layer w5.3: U24.97@889.59,871.22 889.59,837.33 898.25,828.67 968.46,828.67 v1(1000,797.13)
TM4C129_TMS: TP28.1 U24.99 | length 131.8
  Top Layer w5.3: TP28.1@903.9,770 v1(903.9,798.54)
  Bottom Layer w5.3: U24.99@858.1,871.22 858.1,824.48 884.04,798.54 v1(903.9,798.54)
TPS62913_1_EN_SYNC: R146.1 U29.1 | length 86
  Top Layer w10: U29.1@2360.33,781.84 2378.16,781.84 2395,765 v1(2395,755)
  Bottom Layer w10: v1(2395,755) 2396.68,756.68 R146.1@2428.71,756.68
TPS62913_1_FB: R153.1 R154.2 U29.9 | length 130.5
  Top Layer w10: U29.9@2335.73,755.26 2335.73,724.96 2322.33,711.57 R154.2@2322.33,680.3 R153.1@2372.33,680.3
TPS62913_1_NR_SS: C160.1 U29.8 | length 98.1
  Top Layer w10: C160.1@2262.84,683.18 2262.84,684.16 2276.54,697.86 2283.35,697.86 2316.04,730.56 U29.8@2316.04,755.26
TPS62913_1_SCONF: R148.2 U29.10 | length 127.9
  Top Layer w10: U29.10@2355.41,755.26 2355.41,736.62 2363.84,728.19 2376.49,728.19 2410,694.68 R148.2@2447.33,694.68
TPS62913_1_SW: L2.1 U29.2 | length 36.6
  Top Layer w10: U29.2@2353.45,801.52 2390,801.52
TPS62913_2_EN_SYNC: R156.1 U32.1 | length 86
  Top Layer w10: U32.1@2722.01,1414.46 2739.83,1414.46 2756.67,1397.62 v1(2756.67,1387.62)
  Bottom Layer w10: v1(2756.67,1387.62) 2758.35,1389.3 R156.1@2790.38,1389.3
TPS62913_2_FB: R162.1 R163.2 U32.9 | length 213.4
  Top Layer w10: U32.9@2697.4,1387.88 2697.4,1357.58 2684,1344.19 R163.2@2684,1312.92 R162.1@2734,1312.92 2735.55,1314.47 2756.72,1314.47 2762.57,1308.61 2762.57,1257.53 v1(2762.69,1257.41)
TPS62913_2_NR_SS: C177.1 U32.8 | length 97.5
  Top Layer w10: C177.1@2624.51,1315.8 2639.2,1330.48 2645.02,1330.48 2677.72,1363.18 U32.8@2677.72,1387.88
TPS62913_2_SCONF: R160.2 U32.10 | length 162.7
  Top Layer w10: U32.10@2717.09,1387.88 2717.09,1369.24 2725.52,1360.81 2791.39,1360.81 2806.47,1345.72 R160.2@2806.47,1300.85
TPS62913_2_SW: L3.1 U32.2 | length 36.6
  Top Layer w10: U32.2@2715.12,1434.14 2751.67,1434.14
TPS74801_1_BIAS: R150.2 U30.4 | length 83.3
  Top Layer w10: R150.2@5527.75,917.63 5568.86,958.75 U30.4@5594.01,958.75
TPS74801_1_EN: R149.2 U30.5 | length 123.2
  Top Layer w10: R149.2@5527.75,867.63 5549.82,867.63 5562.84,880.65 5562.84,927.3 5574.6,939.06 U30.5@5594.01,939.06
TPS74801_1_FB: R151.1 R152.2 U30.8 | length 162.4
  Top Layer w10: U30.8@5704.25,978.43 5753.33,978.43 5764.13,967.63 R152.2@5764.13,935.98 R151.1@5830.51,935.98
TPS74801_1_PG: R147.1 U30.3 | length 70.7
  Top Layer w10: R147.1@5527.75,967.63 5538.55,978.43 U30.3@5594.01,978.43
TPS74801_1_SS: C166.1 U30.7 | length 64
  Top Layer w10: U30.7@5704.25,958.75 5727.91,958.75 5732.84,953.83 v1(5735,953.83)
  Bottom Layer w10: C166.1@5704.25,954.81 5734.02,954.81 v1(5735,953.83)
TPS74801_2_BIAS: R158.2 U31.4 | length 83.3
  Top Layer w10: R158.2@5527.75,1336.82 5568.86,1377.94 U31.4@5594.01,1377.94
TPS74801_2_EN: R157.2 U31.5 | length 125.2
  Top Layer w10: R157.2@5527.75,1286.82 5553.29,1286.82 5562.84,1296.37 5562.84,1346.49 5574.6,1358.25 U31.5@5594.01,1358.25
TPS74801_2_FB: R159.1 R161.2 U31.8 | length 162.4
  Top Layer w10: U31.8@5704.25,1397.62 5753.33,1397.62 5764.13,1386.82 R161.2@5764.13,1355.17 R159.1@5830.51,1355.17
TPS74801_2_PG: R155.1 U31.3 | length 70.7
  Top Layer w10: R155.1@5527.75,1386.82 5538.55,1397.62 U31.3@5594.01,1397.62
TPS74801_2_SS: C178.1 U31.7 | length 64
  Top Layer w10: U31.7@5704.25,1377.94 5730.08,1377.94 v1(5735,1373.02)
  Bottom Layer w10: C178.1@5704.25,1374 5734.02,1374 v1(5735,1373.02)
TPS75801_2_FB: R372.1 R373.2 U53.4 | length 133.6
  Top Layer w5.3: U53.4@2389.8,330.17 R373.2@2444.32,330.17 R372.1@2444.32,365.99 2467.68,365.99 2473.84,372.16 2473.84,379.87 v1(2476.27,382.3)
TPS75801_VPP_EN: J3.2 R375.2 U53.3 | length 562.9
  Top Layer w5.3: U53.3@2287.43,330.17 2237.34,330.17 2237.34,303.44 2253.87,286.92 2359.92,286.92 2440.68,206.15 2440.68,13.13 J3.2@2475.62,-21.81
TPS75801_VPP_PULL: J3.1 R374.1 | length 103
  Top Layer w5.3: R374.1@2551.35,71.19 2551.35,66.69 2575.62,42.42 J3.1@2575.62,-21.81
TPS_CT: C109.1 U19.6 | length 64
  Top Layer w10: U19.6@1564.33,596.06 1605.2,596.06 C109.1@1621.58,579.69
TPS_VSYS_5V0_ON: R98.1 U19.3 U47.4 | length 800.1
  Top Layer w8: U47.4@975.37,418.4 1006.6,418.4 1020,405 v1(1020,352.5)
  Top Layer w10: v1(1455.63,378.38) 1470,392.75 1470,514.65 1466.81,517.85 1466.81,585.48 1477.39,596.06 U19.3@1489.52,596.06
  SIG 1 w8: v1(1020,352.5) 1031.63,340.87 1418.12,340.87 v1(1455.63,378.38)
TUSB_ADDR: TP5.1 U18.5 | length 125.3
  Top Layer w5.3: U18.5@658.07,165.56 658.07,140.34 673.29,125.12 673.29,104.3 TP5.1@714.09,63.5
TUSB_EN_N: R97.2 U18.11 | length 96.6
  Top Layer w5.3: U18.11@642.32,224.61 642.24,224.69 642.24,237.72 638.2,241.77 638.2,280.6 647.39,289.79 R97.2@673.29,289.79
TUSB_ID: TP3.1 U18.9 | length 199.6
  Top Layer w5.3: U18.9@673.82,224.61 673.9,224.69 673.9,237.72 686.18,250 734.4,250 771.55,287.15 TP3.1@771.55,355.45
TUSB_OUT: R299.1 U21.4 U47.1 | length 385.9
  Top Layer w10: U21.4@924.98,244.13 940.37,244.13 947.5,237 1079,237 1098,256 1098,292.5 1149.88,344.38 R299.1@1149.88,362.5 1127.5,362.5 1108.6,343.6 U47.1@1083.63,343.6
TUSB_OUT1: R89.2 R93.2 U21.1 | length 152.9
  Top Layer w5.3: R89.2@762.51,174.31 780.69,174.31 787.07,167.93 R93.2@819.95,167.93 846.07,167.93 855.97,158.03 877.47,158.03 885.61,166.17 U21.1@885.61,185.87
TUSB_OUT1_R: R89.1 U18.7 | length 52.7
  Top Layer w5.3: U18.7@675.79,187.21 693.62,187.21 706.48,174.35 R89.1@723.14,174.31 R89.1@723.14,174.31
TUSB_OUT2: R90.2 R92.2 U21.2 | length 181.4
  Top Layer w5.3: R90.2@762.51,214.41 784.16,214.41 800.82,231.07 R92.2@819.95,231.07 850,231.07 862.8,218.26 895,218.26 905.3,207.97 U21.2@905.3,185.87
TUSB_OUT2_R: R90.1 U18.8 | length 52.1
  Top Layer w5.3: U18.8@675.79,202.96 694.38,202.96 705.83,214.41 R90.1@723.14,214.41
TUSB_OUT3: R91.1 U18.6 | length 81.7
  Top Layer w5.3: U18.6@673.82,165.56 673.82,145 683.82,135 706.48,135 713.88,127.6 R91.1@713.88,113.69
TUSB_PORT: R95.2 U18.3 | length 73.9
  Top Layer w5.3: R95.2@591.65,106.1 591.65,110.04 626.58,144.96 U18.3@626.58,165.56
TUSB_VBUS_DET: R94.1 U18.4 | length 60.2
  Top Layer w5.3: U18.4@642.32,165.56 642.32,108.55 R94.1@644.6,106.27
USBTYPEC_CC1: J5.A5 R377.2 U18.1 U20.4 U20.7 | length 725.5
  Top Layer w5.3: J5.A5@163.07,389.37 163.44,389.74 181.7,389.74 192.93,400.97 192.93,433.59 207.5,448.16 216.61,457.26 U20.4@233.41,457.26 U20.7@266.29,457.26 R377.2@326.56,457.26 ; R377.2@330.5,457.26 R377.2@326.56,457.26 ; v1(374.31,488.16) 371.88,485.73 335.05,485.73 326.56,477.25 R377.2@326.56,457.26 ; v1(598.87,203.84) 599.31,203.4 624.17,203.4 U18.1@624.61,202.96
  SIG 1 w5.3: v1(374.31,488.16) 434.3,488.16 495.43,427.03 495.43,326.77 598.87,223.34 v1(598.87,203.84)
USBTYPEC_CC2: J5.B5 U18.2 U20.5 U20.6 | length 963.5
  Top Layer w5.3: J5.B5@96.14,320.47 v1(132.33,320.47) ; v1@214.64,418.9 216.25,420.51 216.25,427.92 224.62,436.29 232.13,436.29 U20.5@233.41,437.58 U20.6@266.29,437.58 ; v1(601.36,167.93) 603.79,170.36 603.79,176.24 614.76,187.21 U18.2@624.61,187.21
  SIG 1 w5.3: v1(213.82,418.4) 461.98,418.4 484.83,395.55 484.83,317.68 579.34,223.17 579.34,189.94 v1(601.36,167.93)
  Bottom Layer w5.3: v1(132.33,320.47) 87.93,364.87 87.93,435 96.18,443.25 160.07,443.25 184.92,418.4 v1(213.82,418.4)
VBUS_TYPEC_5V0: C102.1 C103.1 D1.2 J5.A4 J5.A9 J5.B4 J5.B9 L1.1 | length 170.8
  Top Layer w11: J5.B4@96.14,300.79 120.37,300.79 130.22,290.94 J5.A9@163.07,290.94 196.89,290.94 ; J5.B9@96.14,399.21 96.55,398.81 117,398.81 126.07,389.74 v1(127.97,389.74) ; v1(133.1,409.72) 133.44,409.39 162.74,409.39 J5.A4@163.07,409.06
  other v1: 220.99,167.13 249.65,167.13 220.99,195.79 249.65,195.79 220.99,224.45 249.65,224.45 220.99,253.11 249.65,253.11 227.56,281.8 130.59,291.53
VBUS_XDS_5V0: C227.1 C231.1 J34.1 R132.2 R136.2 TP23.1 U45.1 U45.2 U45.8 | length 1973.9
  Top Layer w12: v1(280.11,952.74) 280.11,903.63 U45.8@280.3,903.44 ; 298.96,764.8 305.89,771.73 U45.2@305.89,793.2 ; TP23.1@1057.03,865 v1(1100,865)
  Top Layer w15: J34.1@11.81,1021.01 62.95,1021.01 v1(76.14,1007.82)
  SIG 1 w12: v1(280.11,952.74) 280.11,993.51 249.65,1023.97 249.65,1063.11 210.76,1102 106.61,1102 76.14,1071.53 v1(76.14,1007.82) 77.76,1007.82 85.16,1000.42 103.06,1000.42 v1(104.21,999.27) 104.21,997.65 116.14,985.73 v1(116.14,947.82) 114.99,946.67 114.99,942.35 v1(95.75,923.11) 234.33,784.53 409.53,784.53 471.45,846.45 524.55,846.45 597,774 1030.5,774 1060,803.5 1060,825 v1(1100,865)
  Bottom Layer w12: C227.1@95,874.79 95,922.36 v1(95.75,923.11) ; v1(104.21,999.27) 104.28,999.2 R136.2@133.15,999.2 ; R132.2@1075.19,864.22 1075.58,864.61 1099.61,864.61 v1(1100,865)
VDD_AM263_1V2: C1.1 C2.1 C3.1 C19.2 C20.2 C21.2 C22.2 C29.2 C30.2 C31.2 C32.2 C39.2 C40.2 C41.2 C42.2 C44.2 C45.2 C46.2 C47.2 C49.1 C50.1 C51.1 C52.1 C53.1 C54.1 C55.1 C56.1 C157.1 C158.1 C159.1 L2.2 R153.2 TP10.1 U1.D10 U1.E9 U1.E11 U1.F9 U1.F11 U1.G5 U1.G6 U1.G13 U1.G14 U1.H3 U1.J15 U1.J16 U1.K5 U1.K6 U1.K13 U1.K14 U1.N5 U1.N6 U1.N13 U1.N14 U1.R9 U1.T4 U29.3 | length 1453.2
  Top Layer w10: U29.3@2360.33,821.21 2360.33,845.01 2366.7,851.38
  Top Layer w15: R153.2@2372.33,633.06 2372.33,591.32 v1(2372.51,591.14) ; v1(3444.38,1028.07) U1.H3@3460.12,1012.32 ; v1(3475.87,744.61) U1.T4@3491.62,760.35 ; v1(3507.37,839.09) U1.N5@3523.12,854.84 ; v1(3507.37,933.58) U1.K5@3523.12,949.33 ; v1(3507.37,1059.57) U1.G5@3523.12,1043.82 ; v1(3538.87,839.09) U1.N6@3554.61,854.84 ; v1(3538.87,933.58) U1.K6@3554.61,949.33 ; v1(3538.87,1059.57) U1.G6@3554.61,1043.82 ; v1(3633.35,776.1) U1.R9@3649.1,791.85 ; v1(3633.35,1091.06) U1.F9@3649.1,1075.32 ; v1(3633.35,1122.56) U1.E9@3649.1,1106.81 ; U1.D10@3680.6,1138.31 v1(3696.35,1154.06) ; U1.F11@3712.09,1075.32 v1(3727.84,1091.06) ; U1.E11@3712.09,1106.81 v1(3727.84,1122.56) ; U1.N13@3775.09,854.84 v1(3790.83,839.09) ; U1.K13@3775.09,949.33 v1(3790.83,933.58) ; U1.G13@3775.09,1043.82 v1(3790.83,1059.57) ; U1.N14@3806.58,854.84 v1(3822.33,839.09) ; U1.K14@3806.58,949.33 v1(3822.33,933.58) ; U1.G14@3806.58,1043.82 v1(3822.33,1059.57) ; U1.J15@3838.08,980.83 v1(3853.83,996.57) ; U1.J16@3869.57,980.83 v1(3885.32,996.57)
  Bottom Layer w10: v1(3507.37,839.09) 3509.66,841.38 C56.1@3523,841.38 3536.58,841.38 v1(3538.87,839.09)
  Bottom Layer w12: C40.2@3245.44,945.51 C40.2@3245.84,945.92 ; C54.1@3504.78,952.11 3504.78,936.17 v1(3507.37,933.58) ; v1(3507.37,1059.57) 3510.78,1056.15 C41.2@3523,1056.15 ; C41.2@3523,1056.06 C41.2@3523,1056.15 ; v1(3538.87,933.58) 3543.17,937.89 C46.2@3543.17,952.11 ; v1(3538.87,1059.57) 3535.45,1056.15 C41.2@3523,1056.15 ; v1(3633.35,776.1) 3640.36,783.11 C50.1@3664.85,783.11 ; v1(3727.84,1091.06) 3728.91,1092.13 3728.91,1121.49 v1(3727.84,1122.56) ; C22.2@3777.21,965.08 3777.21,947.2 v1(3790.83,933.58) 3800.53,923.89 3812.64,923.89 v1(3822.33,933.58) ; v1(3790.83,839.09) 3793.94,835.99 3819.23,835.99 v1(3822.33,839.09) ; v1(3790.83,1059.57) 3794.25,1056.15 C19.2@3806.58,1056.15 ; C19.2@3806.58,1056.06 C19.2@3806.58,1056.15 ; v1(3822.33,1059.57) 3818.91,1056.15 C19.2@3806.58,1056.15 ; C55.1@3852.99,965.08 3852.99,995.74 v1(3853.83,996.57)
  Bottom Layer w15: C2.1@3112.14,862.28 3112.14,895 3123.3,906.16 v1(3138.51,906.16) 3138.51,906.97 3145,913.46 C52.1@3145,945.11 ; v1(3138.51,1145.92) C3.1@3138.51,1183.26 ; C1.1@3188.57,862.28 3188.57,898.08 3195.84,905.35 v1(3195.84,906.16) ; v1(3195.62,1145.92) 3195.62,1146.73 3198.24,1149.35 C42.2@3198.24,1189.3 ; C21.2@3245.62,1189.3 v1(3245.62,1145.92) 3245.84,1145.7 C44.2@3245.84,1097.05 ; v1(3245.84,906.16) C40.2@3245.84,945.92 ; C32.2@3295.84,1097.31 3295.84,1145.52 v1(3296.24,1145.92) C49.1@3296.24,1189.3 ; v1(3296.46,906.16) C29.2@3296.46,945.92 ; v1(3633.35,1091.06) 3634.17,1091.06 3635.66,1089.57 C31.2@3651.86,1089.57 ; v1(3633.35,1122.56) 3634.54,1123.75 C30.2@3652.01,1123.75
  other v1: 2422.18,960.22 2472.18,960.22 2522.19,960.22 2567.19,960.22 2422.18,1010.22 2472.18,1010.22 2522.19,1010.22 2567.19,1010.22 2422.18,1060.22 2472.18,1060.22 2522.19,1060.22 2567.19,1060.22
VDD_ETH1_1V1_FILT: C114.1 C115.1 C116.1 C117.1 C118.1 C119.1 C120.1 C121.1 FB3.2 U22.6 U22.31 U22.39 | length 624.7
  Top Layer w10: C120.1@6629.03,579.88 v1(6660,579.88)
  Top Layer w15: FB3.2@6065.25,1161.34 6124.72,1161.34 6133.04,1169.66 C115.1@6194,1169.66 6195.46,1171.12 v1(6225,1171.12) ; C119.1@6247.76,595.04 6262.91,579.88 v1(6290,579.88) 6290.57,580.46 6305.73,580.46 C118.1@6320.32,595.04 ; C116.1@6406.28,768.09 6436.71,768.09 v1(6440,771.38)
  Bottom Layer w10: v1(6290,579.88) U22.31@6341.32,579.88 ; U22.39@6406.28,703.9 C117.1@6406.28,771.46 ; 6406.28,736.71 C117.1@6406.28,771.46 ; v1(6440,771.38) 6439.92,771.46 C117.1@6406.28,771.46 ; U22.6@6609.03,579.88 v1(6660,579.88) C121.1@6696.59,579.88 ; 6641.84,579.88 6676.59,579.88
  other v1: 6247.76,1140.74 6270,1171.12
VDD_ETH1_2V5_FILT: C122.1 C123.1 C124.1 C125.1 C126.1 C127.1 FB4.2 U22.3 U22.9 | length 1183.3
  Top Layer w10: v1(6165,813.52) 6276.67,701.86 6601.7,701.86 6629.03,674.52 C126.1@6629.03,638.94 v1(6660,638.94) 6690,608.94 6690,550.83 v1(6660,520.83) C124.1@6629.03,520.83
  Top Layer w15: FB4.2@5992.49,820.9 6058.74,820.9 C122.1@6060,822.16 6068.63,813.52 C123.1@6130.09,813.52 v1(6165,813.52)
  Bottom Layer w10: U22.9@6609.03,520.83 6641.84,520.83 ; U22.3@6609.03,638.94 v1(6660,638.94) C127.1@6696.59,638.94 ; 6641.84,638.94 6676.59,638.94 ; 6676.59,520.83 6641.84,520.83 ; C125.1@6696.59,520.83 v1(6660,520.83) 6641.84,520.83
VDD_ETH2_1V1_FILT: C191.1 C192.1 C193.1 C194.1 C195.1 C196.1 C197.1 C198.1 FB5.2 U37.6 U37.31 U37.39 | length 559.8
  Top Layer w10: C197.1@6625.03,1529.88 v1(6660,1529.88)
  Top Layer w15: FB5.2@6065.25,1299.44 6124.72,1299.44 C191.1@6129,1303.72 6133.04,1307.76 C192.1@6194,1307.76 6195.46,1309.22 v1(6225,1309.22) ; C196.1@6252.76,1545.04 6267.91,1529.88 v1(6290,1529.88) 6308.71,1529.88 C195.1@6325.32,1546.49 ; C193.1@6406.28,1718.09 6436.71,1718.09 v1(6440,1721.38)
  Bottom Layer w10: v1(6290,1529.88) U37.31@6341.32,1529.88 ; U37.39@6406.28,1653.9 C194.1@6406.28,1721.46 6439.92,1721.46 v1(6440,1721.38) ; U37.6@6609.03,1529.88 v1(6660,1529.88) C198.1@6696.59,1529.88
  other v1: 6267.91,1305
VDD_ETH2_2V5_FILT: C199.1 C200.1 C201.1 C202.1 C203.1 C204.1 FB6.2 U37.3 U37.9 | length 1263
  Top Layer w10: FB6.2@6065.25,1038.64 6128.76,1038.64 C199.1@6128.93,1038.47 6150,1038.47 6159.86,1028.61 C200.1@6184,1028.61 6224.64,1028.61 v1(6225,1028.25) 6282.19,1085.44 6388.39,1085.44 6524.39,1221.44 6524.39,1349.1 6584.47,1409.19 6635.59,1409.19 6660,1433.6 v1(6660,1470.83) ; C203.1@6625.03,1588.94 v1(6660,1588.94) 6690,1558.94 6690,1500.83 v1(6660,1470.83) ; C201.1@6629.03,1470.83 v1(6660,1470.83)
  Bottom Layer w10: U37.9@6609.03,1470.83 v1(6660,1470.83) C202.1@6696.59,1470.83 ; U37.3@6609.03,1588.94 v1(6660,1588.94) C204.1@6696.59,1588.94
VDD_ETH_1V1: C175.1 C176.1 FB3.1 FB5.1 R159.2 TP11.1 U31.9 U31.10 | length 247.4
  Top Layer w10: U31.9@5704.25,1417.31 5733.12,1417.31 5740,1424.19 ; U31.10@5704.25,1436.99 5732.39,1436.99 5759.13,1463.73 C176.1@5759.13,1467.67
  Top Layer w15: FB3.1@6012.1,1160.55 FB5.1@6012.1,1299.44
VDD_ETH_2V5: C164.1 C165.1 FB4.1 FB6.1 R151.2 TP12.1 U30.9 U30.10 | length 331.6
  Top Layer w10: U30.9@5704.25,998.12 5733.12,998.12 5740,1005 ; U30.10@5704.25,1017.8 5732.39,1017.8 5759.13,1044.55 C165.1@5759.13,1048.48 ; v1(5932.5,977.3) 5949.97,994.77 5949.97,1009.88 5951.86,1011.77 5978.73,1038.64 FB6.1@6012.1,1038.64
  Top Layer w15: v1(5932.5,927.3) 5932.5,926.49 5939.34,919.65 FB4.1@5939.34,820.9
